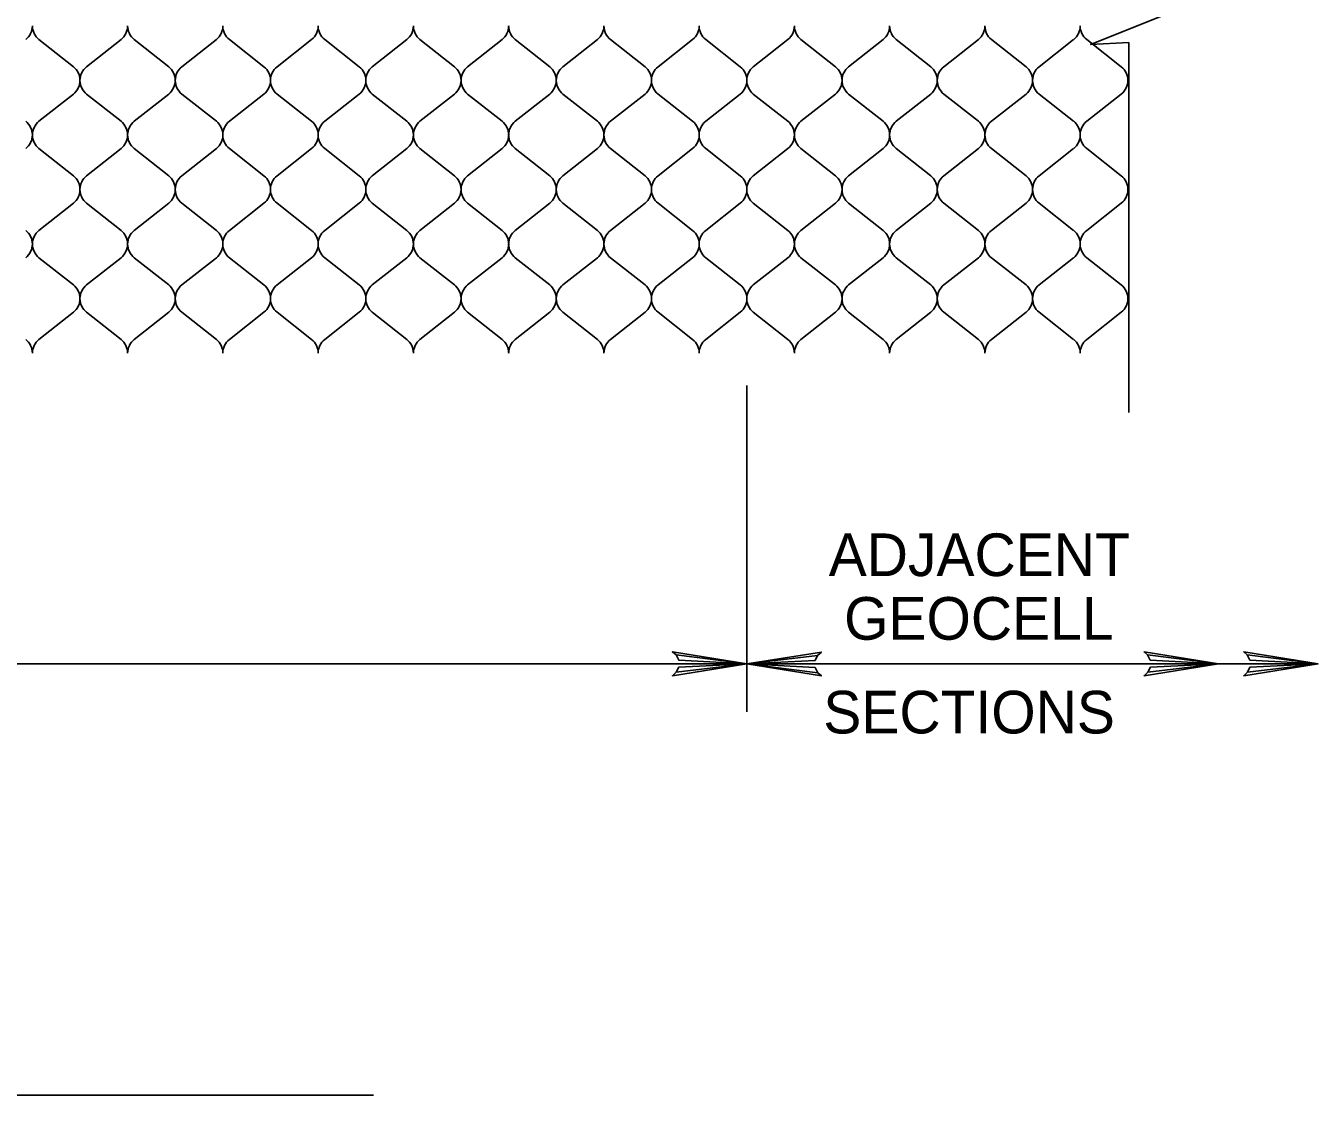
# Model space of a CAD drawing. Extents: x 638850 to 644908, y 297188 to 298900.
# Drawn here: x 640882 to 640972.8, y 298066.7 to 298141.9 of the extents above; entities that cross this region are included whole.
import ezdxf

# ---------------------------------------------------------------- set-up
doc = ezdxf.new("R2010")
doc.units = 0
for name, color, linetype in [('1', 7, 'Continuous'), ('18', 7, 'Continuous'), ('2', 7, 'Continuous'), ('4', 7, 'Continuous'), ('7', 7, 'Continuous')]:
    doc.layers.add(name, color=color, linetype=linetype)

msp = doc.modelspace()

# ---------------------------------------------------------------- linework, layer by layer
at = {"layer": '1'}
msp.add_lwpolyline([(640959.518, 298140.763), (640956.832, 298140.627), (640961.929, 298142.665), (640959.612, 298143.591)], dxfattribs=at)
at = {"layer": '18'}
for points in [[(640927.682, 298097.672), (640927.867, 298097.31), (640932.664, 298097.047), (640927.682, 298097.672), (640927.426, 298097.89), (640932.664, 298097.047), (640927.871, 298096.808), (640927.696, 298096.453), (640932.664, 298097.047), (640927.426, 298096.214), (640927.696, 298096.453)], [(640937.645, 298096.421), (640937.461, 298096.781), (640932.664, 298097.047), (640937.645, 298096.421), (640937.902, 298096.203), (640932.664, 298097.047), (640937.456, 298097.283), (640937.632, 298097.641), (640932.664, 298097.047), (640937.902, 298097.879), (640937.632, 298097.641)], [(640960.845, 298097.672), (640961.032, 298097.312), (640965.829, 298097.046), (640960.845, 298097.672), (640960.591, 298097.89), (640965.829, 298097.046), (640961.037, 298096.81), (640960.861, 298096.452), (640965.829, 298097.046), (640960.591, 298096.214), (640960.861, 298096.452)], [(640967.852, 298097.672), (640968.039, 298097.312), (640972.836, 298097.046), (640967.852, 298097.672), (640967.598, 298097.89), (640972.836, 298097.046), (640968.041, 298096.81), (640967.868, 298096.452), (640972.836, 298097.046), (640967.598, 298096.214), (640967.868, 298096.452)]]:
    msp.add_lwpolyline(points, dxfattribs=at)
at = {"layer": '2'}
for p, q in [((640882.878, 298140.972), (640885.31, 298139.053)), ((640886.226, 298139.053), (640888.658, 298140.972)), ((640889.576, 298140.972), (640892.008, 298139.053)), ((640892.924, 298139.053), (640895.357, 298140.972)), ((640896.274, 298140.972), (640898.706, 298139.053)), ((640899.625, 298139.053), (640902.057, 298140.972)), ((640902.975, 298140.972), (640905.407, 298139.053)), ((640906.321, 298139.053), (640908.753, 298140.972)), ((640909.671, 298140.972), (640912.103, 298139.053)), ((640913.021, 298139.053), (640915.454, 298140.972)), ((640916.371, 298140.972), (640918.803, 298139.053)), ((640919.72, 298139.053), (640922.152, 298140.972)), ((640923.07, 298140.972), (640925.502, 298139.053)), ((640926.418, 298139.053), (640928.85, 298140.972)), ((640929.768, 298140.972), (640932.2, 298139.053)), ((640933.114, 298139.053), (640935.546, 298140.972)), ((640936.464, 298140.972), (640938.896, 298139.053)), ((640939.812, 298139.053), (640942.244, 298140.972)), ((640943.162, 298140.972), (640945.594, 298139.053)), ((640946.51, 298139.053), (640948.943, 298140.972)), ((640949.86, 298140.972), (640952.292, 298139.053)), ((640953.211, 298139.053), (640955.643, 298140.972)), ((640956.561, 298140.972), (640958.993, 298139.053)), ((640885.31, 298137.133), (640882.878, 298135.215)), ((640888.658, 298135.215), (640886.226, 298137.133)), ((640892.008, 298137.133), (640889.576, 298135.215)), ((640895.357, 298135.215), (640892.924, 298137.133)), ((640898.706, 298137.133), (640896.274, 298135.215)), ((640902.057, 298135.215), (640899.625, 298137.133)), ((640905.407, 298137.133), (640902.975, 298135.215)), ((640908.753, 298135.215), (640906.321, 298137.133)), ((640912.103, 298137.133), (640909.671, 298135.215)), ((640915.454, 298135.215), (640913.021, 298137.133)), ((640918.803, 298137.133), (640916.371, 298135.215)), ((640922.152, 298135.215), (640919.72, 298137.133)), ((640925.502, 298137.133), (640923.07, 298135.215)), ((640928.85, 298135.215), (640926.418, 298137.133)), ((640932.2, 298137.133), (640929.768, 298135.215)), ((640935.546, 298135.215), (640933.114, 298137.133)), ((640938.896, 298137.133), (640936.464, 298135.215)), ((640942.244, 298135.215), (640939.812, 298137.133)), ((640945.594, 298137.133), (640943.162, 298135.215)), ((640948.943, 298135.215), (640946.51, 298137.133)), ((640952.292, 298137.133), (640949.86, 298135.215)), ((640955.643, 298135.215), (640953.211, 298137.133)), ((640958.993, 298137.133), (640956.561, 298135.215)), ((640882.878, 298133.295), (640885.31, 298131.376)), ((640886.226, 298131.376), (640888.658, 298133.295)), ((640889.576, 298133.295), (640892.008, 298131.376)), ((640892.924, 298131.376), (640895.357, 298133.295)), ((640896.274, 298133.295), (640898.706, 298131.376)), ((640899.625, 298131.376), (640902.057, 298133.295)), ((640902.975, 298133.295), (640905.407, 298131.376)), ((640906.321, 298131.376), (640908.753, 298133.295)), ((640909.671, 298133.295), (640912.103, 298131.376)), ((640913.021, 298131.376), (640915.454, 298133.295)), ((640916.371, 298133.295), (640918.803, 298131.376)), ((640919.72, 298131.376), (640922.152, 298133.295)), ((640923.07, 298133.295), (640925.502, 298131.376)), ((640926.418, 298131.376), (640928.85, 298133.295)), ((640929.768, 298133.295), (640932.2, 298131.376)), ((640933.114, 298131.379), (640935.546, 298133.297)), ((640936.464, 298133.297), (640938.896, 298131.379)), ((640939.812, 298131.379), (640942.244, 298133.297)), ((640943.162, 298133.297), (640945.594, 298131.379)), ((640946.51, 298131.379), (640948.943, 298133.297)), ((640949.86, 298133.297), (640952.292, 298131.379)), ((640953.211, 298131.379), (640955.643, 298133.297)), ((640956.561, 298133.297), (640958.993, 298131.379)), ((640885.31, 298129.456), (640882.878, 298127.538)), ((640888.658, 298127.538), (640886.226, 298129.456)), ((640892.008, 298129.456), (640889.576, 298127.538)), ((640895.357, 298127.538), (640892.924, 298129.456)), ((640898.706, 298129.456), (640896.274, 298127.538)), ((640902.057, 298127.538), (640899.625, 298129.456)), ((640905.407, 298129.456), (640902.975, 298127.538)), ((640908.753, 298127.538), (640906.321, 298129.456)), ((640912.103, 298129.456), (640909.671, 298127.538)), ((640915.454, 298127.538), (640913.021, 298129.456)), ((640918.803, 298129.456), (640916.371, 298127.538)), ((640922.152, 298127.538), (640919.72, 298129.456)), ((640925.502, 298129.456), (640923.07, 298127.538)), ((640928.85, 298127.538), (640926.418, 298129.456)), ((640932.2, 298129.456), (640929.768, 298127.538)), ((640935.546, 298127.54), (640933.114, 298129.458)), ((640938.896, 298129.458), (640936.464, 298127.54)), ((640942.244, 298127.54), (640939.812, 298129.458)), ((640945.594, 298129.458), (640943.162, 298127.54)), ((640948.943, 298127.54), (640946.51, 298129.458)), ((640952.292, 298129.458), (640949.86, 298127.54)), ((640955.643, 298127.54), (640953.211, 298129.458)), ((640958.993, 298129.458), (640956.561, 298127.54)), ((640882.878, 298125.62), (640885.31, 298123.702)), ((640886.226, 298123.702), (640888.658, 298125.62)), ((640889.576, 298125.62), (640892.008, 298123.702)), ((640892.924, 298123.702), (640895.357, 298125.62)), ((640896.274, 298125.62), (640898.706, 298123.702)), ((640899.625, 298123.702), (640902.057, 298125.62)), ((640902.975, 298125.62), (640905.407, 298123.702)), ((640906.321, 298123.702), (640908.753, 298125.62)), ((640909.671, 298125.62), (640912.103, 298123.702)), ((640913.021, 298123.702), (640915.454, 298125.62)), ((640916.371, 298125.62), (640918.803, 298123.702)), ((640919.72, 298123.702), (640922.152, 298125.62)), ((640923.07, 298125.62), (640925.502, 298123.702)), ((640926.418, 298123.702), (640928.85, 298125.62)), ((640929.768, 298125.62), (640932.2, 298123.702)), ((640933.114, 298123.702), (640935.546, 298125.62)), ((640936.464, 298125.62), (640938.896, 298123.702)), ((640939.812, 298123.702), (640942.244, 298125.62)), ((640943.162, 298125.62), (640945.594, 298123.702)), ((640946.51, 298123.702), (640948.943, 298125.62)), ((640949.86, 298125.62), (640952.292, 298123.702)), ((640953.211, 298123.702), (640955.643, 298125.62)), ((640956.561, 298125.62), (640958.993, 298123.702)), ((640885.31, 298121.781), (640882.878, 298119.863)), ((640888.658, 298119.863), (640886.226, 298121.781)), ((640892.008, 298121.781), (640889.576, 298119.863)), ((640895.357, 298119.863), (640892.924, 298121.781)), ((640898.706, 298121.781), (640896.274, 298119.863)), ((640902.057, 298119.863), (640899.625, 298121.781)), ((640905.407, 298121.781), (640902.975, 298119.863)), ((640908.753, 298119.863), (640906.321, 298121.781)), ((640912.103, 298121.781), (640909.671, 298119.863)), ((640915.454, 298119.863), (640913.021, 298121.781)), ((640918.803, 298121.781), (640916.371, 298119.863)), ((640922.152, 298119.863), (640919.72, 298121.781)), ((640925.502, 298121.781), (640923.07, 298119.863)), ((640928.85, 298119.863), (640926.418, 298121.781)), ((640932.2, 298121.781), (640929.768, 298119.863)), ((640935.546, 298119.863), (640933.114, 298121.781)), ((640938.896, 298121.781), (640936.464, 298119.863)), ((640942.244, 298119.863), (640939.812, 298121.781)), ((640945.594, 298121.781), (640943.162, 298119.863)), ((640948.943, 298119.863), (640946.51, 298121.781)), ((640952.292, 298121.781), (640949.86, 298119.863)), ((640955.643, 298119.863), (640953.211, 298121.781)), ((640958.993, 298121.781), (640956.561, 298119.863))]:
    msp.add_line(p, q, dxfattribs=at)
for centre, start, end in [((640881.184, 298141.932), 308.94823, 0), ((640883.654, 298141.932), 180, 231.05177), ((640887.882, 298141.932), 308.94823, 0), ((640890.352, 298141.932), 180, 231.05177), ((640894.581, 298141.932), 308.94823, 0), ((640897.05, 298141.932), 180, 231.05177), ((640901.281, 298141.932), 308.94823, 0), ((640903.751, 298141.932), 180, 231.05177), ((640907.977, 298141.932), 308.94823, 0), ((640910.447, 298141.932), 180, 231.05177), ((640914.678, 298141.932), 308.94823, 0), ((640917.147, 298141.932), 180, 231.05177), ((640921.376, 298141.932), 308.94823, 0), ((640923.845, 298141.932), 180, 231.05177), ((640928.074, 298141.932), 308.94823, 0), ((640930.544, 298141.932), 180, 231.05177), ((640934.77, 298141.932), 308.94823, 0), ((640937.24, 298141.932), 180, 231.05177), ((640941.468, 298141.932), 308.94823, 0), ((640943.938, 298141.932), 180, 231.05177), ((640948.167, 298141.932), 308.94823, 0), ((640950.636, 298141.932), 180, 231.05177), ((640954.867, 298141.932), 308.94823, 0), ((640957.337, 298141.932), 180, 231.05177), ((640884.533, 298138.093), 0, 51.05177), ((640887.003, 298138.093), 128.94823, 180), ((640891.232, 298138.093), 0, 51.05177), ((640893.701, 298138.093), 128.94823, 180), ((640897.93, 298138.093), 0, 51.05177), ((640900.402, 298138.093), 128.94823, 180), ((640904.63, 298138.093), 0, 51.05177), ((640907.098, 298138.093), 128.94823, 180), ((640911.326, 298138.093), 0, 51.05177), ((640913.798, 298138.093), 128.94823, 180), ((640918.027, 298138.093), 0, 51.05177), ((640920.496, 298138.093), 128.94823, 180), ((640924.725, 298138.093), 0, 51.05177), ((640927.195, 298138.093), 128.94823, 180), ((640931.423, 298138.093), 0, 51.05177), ((640933.891, 298138.093), 128.94823, 180), ((640938.119, 298138.093), 0, 51.05177), ((640940.589, 298138.093), 128.94823, 180), ((640944.818, 298138.093), 0, 51.05177), ((640947.287, 298138.093), 128.94823, 180), ((640951.516, 298138.093), 0, 51.05177), ((640953.988, 298138.093), 128.94823, 180), ((640958.216, 298138.093), 0, 51.05177), ((640884.533, 298138.093), 308.94823, 0), ((640887.003, 298138.093), 180, 231.05177), ((640891.232, 298138.093), 308.94823, 0), ((640893.701, 298138.093), 180, 231.05177), ((640897.93, 298138.093), 308.94823, 0), ((640900.402, 298138.093), 180, 231.05177), ((640904.63, 298138.093), 308.94823, 0), ((640907.098, 298138.093), 180, 231.05177), ((640911.326, 298138.093), 308.94823, 0), ((640913.798, 298138.093), 180, 231.05177), ((640918.027, 298138.093), 308.94823, 0), ((640920.496, 298138.093), 180, 231.05177), ((640924.725, 298138.093), 308.94823, 0), ((640927.195, 298138.093), 180, 231.05177), ((640931.423, 298138.093), 308.94823, 0), ((640933.891, 298138.093), 180, 231.05177), ((640938.119, 298138.093), 308.94823, 0), ((640940.589, 298138.093), 180, 231.05177), ((640944.818, 298138.093), 308.94823, 0), ((640947.287, 298138.093), 180, 231.05177), ((640951.516, 298138.093), 308.94823, 0), ((640953.988, 298138.093), 180, 231.05177), ((640958.216, 298138.093), 308.94823, 0), ((640881.184, 298134.255), 0, 51.05177), ((640883.654, 298134.255), 128.94823, 180), ((640887.882, 298134.255), 0, 51.05177), ((640890.352, 298134.255), 128.94823, 180), ((640894.581, 298134.255), 0, 51.05177), ((640897.05, 298134.255), 128.94823, 180), ((640901.281, 298134.255), 0, 51.05177), ((640903.751, 298134.255), 128.94823, 180), ((640907.977, 298134.255), 0, 51.05177), ((640910.447, 298134.255), 128.94823, 180), ((640914.678, 298134.255), 0, 51.05177), ((640917.147, 298134.255), 128.94823, 180), ((640921.376, 298134.255), 0, 51.05177), ((640923.845, 298134.255), 128.94823, 180), ((640928.074, 298134.255), 0, 51.05177), ((640930.544, 298134.255), 128.94823, 180), ((640934.77, 298134.255), 0, 51.05177), ((640937.24, 298134.255), 128.94823, 180), ((640941.468, 298134.255), 0, 51.05177), ((640943.938, 298134.255), 128.94823, 180), ((640948.167, 298134.255), 0, 51.05177), ((640950.636, 298134.255), 128.94823, 180), ((640954.867, 298134.255), 0, 51.05177), ((640957.337, 298134.255), 128.94823, 180), ((640881.184, 298134.255), 308.94823, 0), ((640883.654, 298134.255), 180, 231.05177), ((640887.882, 298134.255), 308.94823, 0), ((640890.352, 298134.255), 180, 231.05177), ((640894.581, 298134.255), 308.94823, 0), ((640897.05, 298134.255), 180, 231.05177), ((640901.281, 298134.255), 308.94823, 0), ((640903.751, 298134.255), 180, 231.05177), ((640907.977, 298134.255), 308.94823, 0), ((640910.447, 298134.255), 180, 231.05177), ((640914.678, 298134.255), 308.94823, 0), ((640917.147, 298134.255), 180, 231.05177), ((640921.376, 298134.255), 308.94823, 0), ((640923.845, 298134.255), 180, 231.05177), ((640928.074, 298134.255), 308.94823, 0), ((640930.544, 298134.255), 180, 231.05177), ((640934.77, 298134.257), 308.94823, 0), ((640937.24, 298134.257), 180, 231.05177), ((640941.468, 298134.257), 308.94823, 0), ((640943.938, 298134.257), 180, 231.05177), ((640948.167, 298134.257), 308.94823, 0), ((640950.636, 298134.257), 180, 231.05177), ((640954.867, 298134.257), 308.94823, 0), ((640957.337, 298134.257), 180, 231.05177), ((640884.533, 298130.416), 0, 51.05177), ((640887.003, 298130.416), 128.94823, 180), ((640891.232, 298130.416), 0, 51.05177), ((640893.701, 298130.416), 128.94823, 180), ((640897.93, 298130.416), 0, 51.05177), ((640900.402, 298130.416), 128.94823, 180), ((640904.63, 298130.416), 0, 51.05177), ((640907.098, 298130.416), 128.94823, 180), ((640911.326, 298130.416), 0, 51.05177), ((640913.798, 298130.416), 128.94823, 180), ((640918.027, 298130.416), 0, 51.05177), ((640920.496, 298130.416), 128.94823, 180), ((640924.725, 298130.416), 0, 51.05177), ((640927.195, 298130.416), 128.94823, 180), ((640931.423, 298130.416), 0, 51.05177), ((640933.891, 298130.419), 128.94823, 180), ((640938.119, 298130.419), 0, 51.05177), ((640940.589, 298130.419), 128.94823, 180), ((640944.818, 298130.419), 0, 51.05177), ((640947.287, 298130.419), 128.94823, 180), ((640951.516, 298130.419), 0, 51.05177), ((640953.988, 298130.419), 128.94823, 180), ((640958.216, 298130.419), 0, 51.05177), ((640884.533, 298130.416), 308.94823, 0), ((640887.003, 298130.416), 180, 231.05177), ((640891.232, 298130.416), 308.94823, 0), ((640893.701, 298130.416), 180, 231.05177), ((640897.93, 298130.416), 308.94823, 0), ((640900.402, 298130.416), 180, 231.05177), ((640904.63, 298130.416), 308.94823, 0), ((640907.098, 298130.416), 180, 231.05177), ((640911.326, 298130.416), 308.94823, 0), ((640913.798, 298130.416), 180, 231.05177), ((640918.027, 298130.416), 308.94823, 0), ((640920.496, 298130.416), 180, 231.05177), ((640924.725, 298130.416), 308.94823, 0), ((640927.195, 298130.416), 180, 231.05177), ((640931.423, 298130.416), 308.94823, 0), ((640933.891, 298130.419), 180, 231.05177), ((640938.119, 298130.419), 308.94823, 0), ((640940.589, 298130.419), 180, 231.05177), ((640944.818, 298130.419), 308.94823, 0), ((640947.287, 298130.419), 180, 231.05177), ((640951.516, 298130.419), 308.94823, 0), ((640953.988, 298130.419), 180, 231.05177), ((640958.216, 298130.419), 308.94823, 0), ((640881.184, 298126.578), 0, 51.05177), ((640883.654, 298126.578), 128.94823, 180), ((640887.882, 298126.578), 0, 51.05177), ((640890.352, 298126.578), 128.94823, 180), ((640894.581, 298126.578), 0, 51.05177), ((640897.05, 298126.578), 128.94823, 180), ((640901.281, 298126.578), 0, 51.05177), ((640903.751, 298126.578), 128.94823, 180), ((640907.977, 298126.578), 0, 51.05177), ((640910.447, 298126.578), 128.94823, 180), ((640914.678, 298126.578), 0, 51.05177), ((640917.147, 298126.578), 128.94823, 180), ((640921.376, 298126.578), 0, 51.05177), ((640923.845, 298126.578), 128.94823, 180), ((640928.074, 298126.578), 0, 51.05177), ((640930.544, 298126.578), 128.94823, 180), ((640934.77, 298126.58), 0, 51.05177), ((640937.24, 298126.58), 128.94823, 180), ((640941.468, 298126.58), 0, 51.05177), ((640943.938, 298126.58), 128.94823, 180), ((640948.167, 298126.58), 0, 51.05177), ((640950.636, 298126.58), 128.94823, 180), ((640954.867, 298126.58), 0, 51.05177), ((640957.337, 298126.58), 128.94823, 180), ((640881.184, 298126.58), 308.94823, 0), ((640883.654, 298126.58), 180, 231.05177), ((640887.882, 298126.58), 308.94823, 0), ((640890.352, 298126.58), 180, 231.05177), ((640894.581, 298126.58), 308.94823, 0), ((640897.05, 298126.58), 180, 231.05177), ((640901.281, 298126.58), 308.94823, 0), ((640903.751, 298126.58), 180, 231.05177), ((640907.977, 298126.58), 308.94823, 0), ((640910.447, 298126.58), 180, 231.05177), ((640914.678, 298126.58), 308.94823, 0), ((640917.147, 298126.58), 180, 231.05177), ((640921.376, 298126.58), 308.94823, 0), ((640923.845, 298126.58), 180, 231.05177), ((640928.074, 298126.58), 308.94823, 0), ((640930.544, 298126.58), 180, 231.05177), ((640934.77, 298126.58), 308.94823, 0), ((640937.24, 298126.58), 180, 231.05177), ((640941.468, 298126.58), 308.94823, 0), ((640943.938, 298126.58), 180, 231.05177), ((640948.167, 298126.58), 308.94823, 0), ((640950.636, 298126.58), 180, 231.05177), ((640954.867, 298126.58), 308.94823, 0), ((640957.337, 298126.58), 180, 231.05177), ((640884.533, 298122.742), 0, 51.05177), ((640887.003, 298122.742), 128.94823, 180), ((640891.232, 298122.742), 0, 51.05177), ((640893.701, 298122.742), 128.94823, 180), ((640897.93, 298122.742), 0, 51.05177), ((640900.402, 298122.742), 128.94823, 180), ((640904.63, 298122.742), 0, 51.05177), ((640907.098, 298122.742), 128.94823, 180), ((640911.326, 298122.742), 0, 51.05177), ((640913.798, 298122.742), 128.94823, 180), ((640918.027, 298122.742), 0, 51.05177), ((640920.496, 298122.742), 128.94823, 180), ((640924.725, 298122.742), 0, 51.05177), ((640927.195, 298122.742), 128.94823, 180), ((640931.423, 298122.742), 0, 51.05177), ((640933.891, 298122.742), 128.94823, 180), ((640938.119, 298122.742), 0, 51.05177), ((640940.589, 298122.742), 128.94823, 180), ((640944.818, 298122.742), 0, 51.05177), ((640947.287, 298122.742), 128.94823, 180), ((640951.516, 298122.742), 0, 51.05177), ((640953.988, 298122.742), 128.94823, 180), ((640958.216, 298122.742), 0, 51.05177), ((640884.533, 298122.742), 308.94823, 0), ((640887.003, 298122.742), 180, 231.05177), ((640891.232, 298122.742), 308.94823, 0), ((640893.701, 298122.742), 180, 231.05177), ((640897.93, 298122.742), 308.94823, 0), ((640900.402, 298122.742), 180, 231.05177), ((640904.63, 298122.742), 308.94823, 0), ((640907.098, 298122.742), 180, 231.05177), ((640911.326, 298122.742), 308.94823, 0), ((640913.798, 298122.742), 180, 231.05177), ((640918.027, 298122.742), 308.94823, 0), ((640920.496, 298122.742), 180, 231.05177), ((640924.725, 298122.742), 308.94823, 0), ((640927.195, 298122.742), 180, 231.05177), ((640931.423, 298122.742), 308.94823, 0), ((640933.891, 298122.742), 180, 231.05177), ((640938.119, 298122.742), 308.94823, 0), ((640940.589, 298122.742), 180, 231.05177), ((640944.818, 298122.742), 308.94823, 0), ((640947.287, 298122.742), 180, 231.05177), ((640951.516, 298122.742), 308.94823, 0), ((640953.988, 298122.742), 180, 231.05177), ((640958.216, 298122.742), 308.94823, 0), ((640881.184, 298118.903), 0, 51.05177), ((640883.654, 298118.903), 128.94823, 180), ((640887.882, 298118.903), 0, 51.05177), ((640890.352, 298118.903), 128.94823, 180), ((640894.581, 298118.903), 0, 51.05177), ((640897.05, 298118.903), 128.94823, 180), ((640901.281, 298118.903), 0, 51.05177), ((640903.751, 298118.903), 128.94823, 180), ((640907.977, 298118.903), 0, 51.05177), ((640910.447, 298118.903), 128.94823, 180), ((640914.678, 298118.903), 0, 51.05177), ((640917.147, 298118.903), 128.94823, 180), ((640921.376, 298118.903), 0, 51.05177), ((640923.845, 298118.903), 128.94823, 180), ((640928.074, 298118.903), 0, 51.05177), ((640930.544, 298118.903), 128.94823, 180), ((640934.77, 298118.903), 0, 51.05177), ((640937.24, 298118.903), 128.94823, 180), ((640941.468, 298118.903), 0, 51.05177), ((640943.938, 298118.903), 128.94823, 180), ((640948.167, 298118.903), 0, 51.05177), ((640950.636, 298118.903), 128.94823, 180), ((640954.867, 298118.903), 0, 51.05177), ((640957.337, 298118.903), 128.94823, 180)]:
    msp.add_arc(centre, 1.235, start, end, dxfattribs=at)
at = {"layer": '4'}
msp.add_line((640785.268, 298066.702), (640906.405, 298066.702), dxfattribs=at)
at = {"layer": '7'}
for p, q in [((640959.518, 298140.763), (640959.518, 298114.728)), ((640932.663, 298116.621), (640932.663, 298093.671)), ((640738.385, 298097.046), (640932.663, 298097.046)), ((640972.836, 298097.046), (640932.663, 298097.046))]:
    msp.add_line(p, q, dxfattribs=at)

# ---------------------------------------------------------------- texts
at = {"layer": '4'}
for s, p in [('ADJACENT', (640938.417, 298103.22)), ('GEOCELL', (640939.498, 298098.744)), ('SECTIONS', (640938.036, 298092.15))]:
    msp.add_text(s, height=3, dxfattribs=at).set_placement(p)

doc.saveas('drawing.dxf')
